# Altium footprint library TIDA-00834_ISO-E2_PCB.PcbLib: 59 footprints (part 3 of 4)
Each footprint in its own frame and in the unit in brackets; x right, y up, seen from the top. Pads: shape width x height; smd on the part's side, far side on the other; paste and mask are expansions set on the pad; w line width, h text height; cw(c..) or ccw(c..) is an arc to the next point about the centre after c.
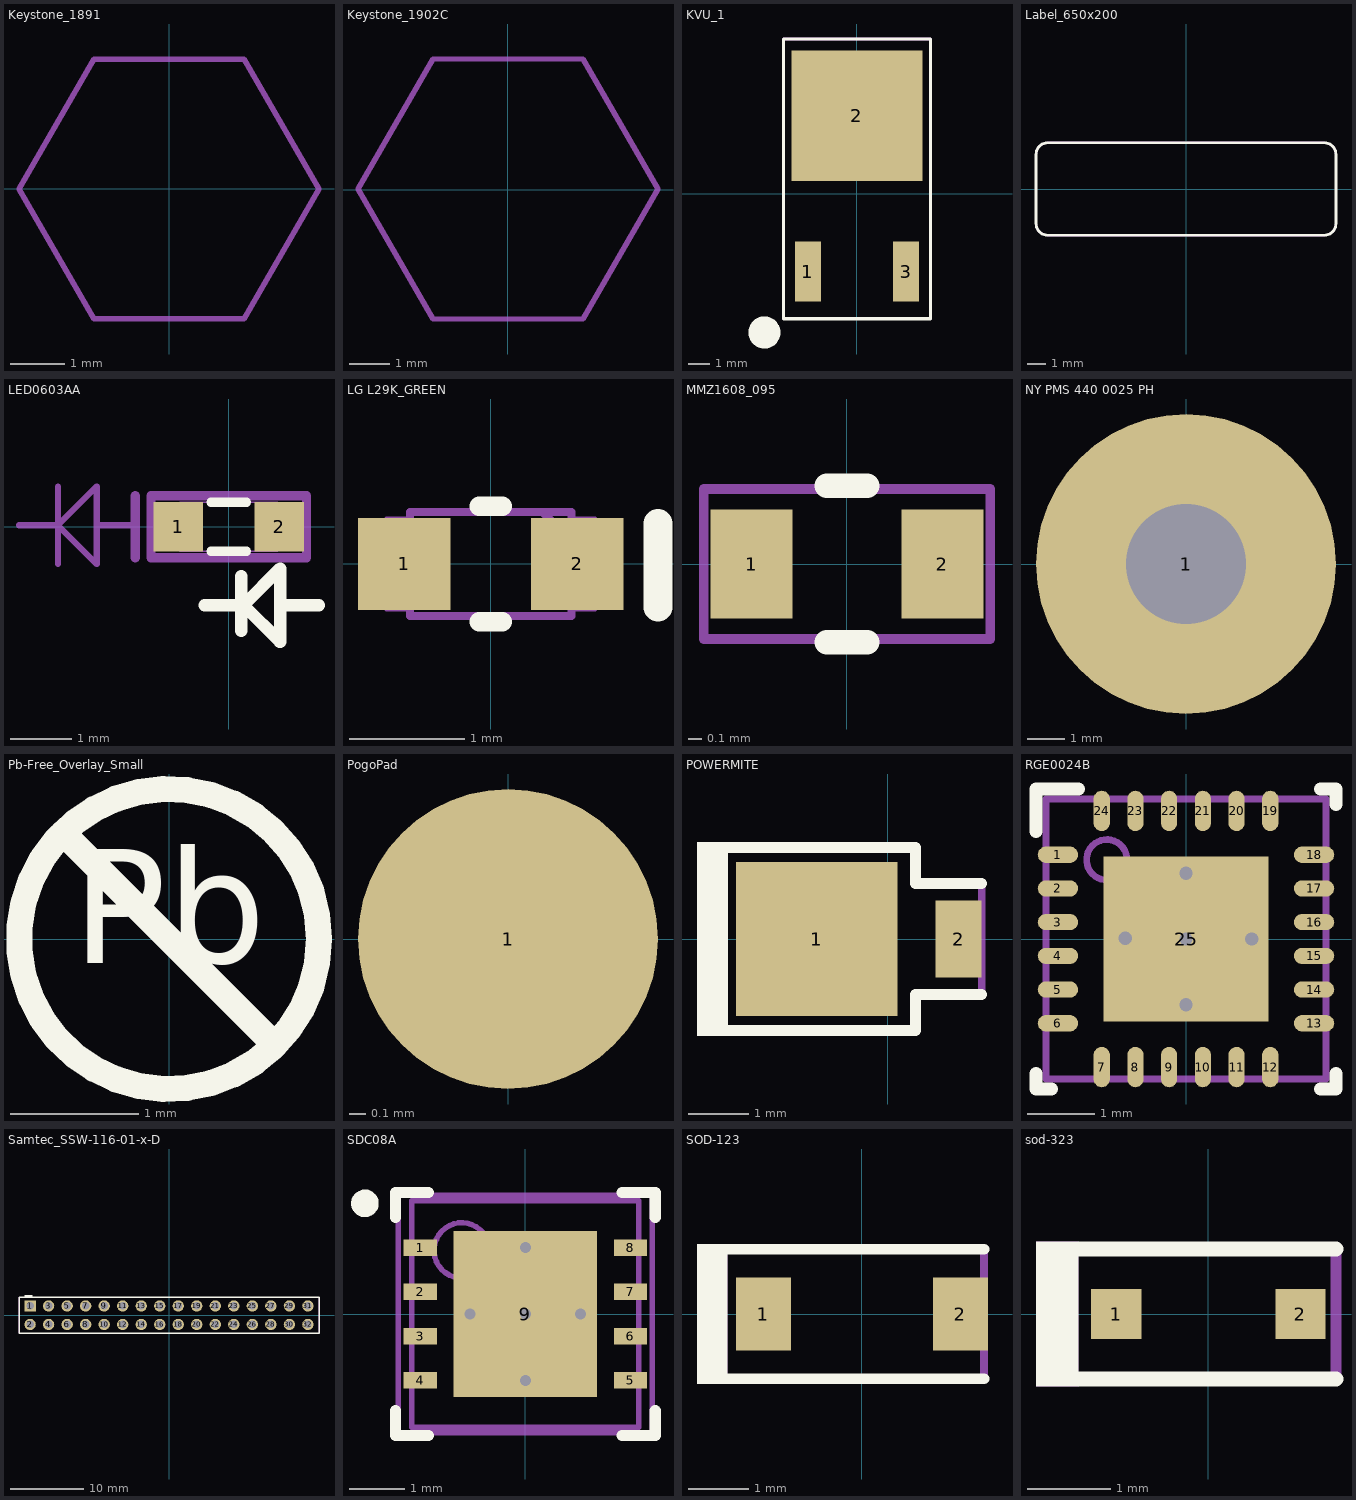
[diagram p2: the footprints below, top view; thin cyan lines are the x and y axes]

## Keystone_1891 [mm] "3/16 Hex Female Standoff"
height 6.35
Mechanical 5:
  lines w0.1: -2.742,0 -1.371,-2.375 0,-2.375 1.371,-2.375 2.742,0 1.371,2.375 0,2.375 -1.371,2.375 -2.742,0
  text ".Designator" at -0.66,-0.174 h0.64
3D body "keystone-PN1891.stp": height 6.22, standoff -0.13, extent -2.742,-2.375 2.742,2.375

## Keystone_1902C [mm] "Hex Standoff, 4-40 threaded, nylon"
height 12.7
Mechanical 5:
  lines w0.127: -3.69,0.012 -1.843,-3.188 1.852,-3.188 3.7,0.012 1.852,3.212 -1.843,3.212 -3.69,0.012
  text ".Designator" at -1.524,-0.508 h1.02
3D body "Keystone_1902C.stp": height 12.73, standoff 0.03, extent -3.682,-3.2 3.708,3.2

## KVU_1 [mm]
height 2.39
pads (3):
  rect 1.2x2.8 smd: 1(-2.29,-3.635) 3(2.29,-3.635)
  rect 6.096x6.096 smd: 2(0,3.635)
Top Overlay:
  circle w0.889: c-4.318,-6.477 r0.305
  lines w0.152: -3.429,-5.841 -3.429,7.216 3.429,7.216 3.429,-5.841 -3.429,-5.841
Mechanical 5:
  lines w0.127: -3.429,-5.841 3.429,-5.841 3.429,7.216 -3.429,7.216 -3.429,-5.841
  text ".Designator" at 0,1.524 h0.64

## Label_650x200 [mm] "Thermal Transfer Label"
height 0.025
Top Overlay:
  lines w0.152: -8.255,-1.905 ccw(c-7.62,-1.905) -7.62,-2.54 7.62,-2.54 ccw(c7.62,-1.905) 8.255,-1.905 8.255,1.905 ccw(c7.62,1.905) 7.62,2.54 -7.62,2.54 ccw(c-7.62,1.905) -8.255,1.905 -8.255,-1.905
Mechanical 5:
  lines w0.127: -8.255,-1.905 ccw(c-7.62,-1.905) -7.62,-2.54 7.62,-2.54 ccw(c7.62,-1.905) 8.255,-1.905 8.255,1.905 ccw(c7.62,1.905) 7.62,2.54 -7.62,2.54 ccw(c-7.62,1.905) -8.255,1.905 -8.255,-1.905
  text ".Designator" at -1.524,-0.508 h0.64
3D body: height 0.03, standoff 0, extent -8.256,-2.541 8.256,2.541

## LED0603AA [mil]
height 118.11
pads (2):
  rect 32x32 smd: 1(-32.48,0) 2(32.48,0)
Top Overlay:
  lines w6: -11.42,-15.75 11.42,-15.75 ; -11.42,15.75 11.42,15.75
  lines w8: -15.58,-50.44 9.42,-50.44 33,-26.85 33,-73.81 ; 8,-66.85 8,-31.85 ; 9.62,-50.44 33,-73.81 ; 32.79,-73.81 33,-73.81 ; 33,-50.33 58,-50.33
Mechanical 5:
  lines w6: -60,-20 -60,20 ; -50,-20 50,-20 50,20 -50,20 -50,-20
  text ".designator" at -36,-57 h25
Mechanical 15:
  lines w1: -31.5,-15.75 31.5,-15.75 31.5,15.75 -31.5,15.75 -31.5,-15.75
  lines w3.94: -134.79,0.96 -109.79,0.96 ; -109.79,-24.04 -109.79,25.96 ; -84.79,0.96 -59.79,0.96 ; -109.79,0.96 -84.79,25.96 -84.79,-24.04 -109.79,0.96

## LG L29K_GREEN [mm] "OSRAM"
height 0.67
pads (2):
  rect 0.8x0.8 smd: 1(-0.75,0) 2(0.75,0)
Top Overlay:
  lines w0.17: -0.1,-0.5 0.1,-0.5 ; -0.1,0.5 0.1,0.5
  lines w0.25: 1.45,-0.375 1.45,0.35
Top Paste:
  rectangle: 0.5,-0.35 1.1,0.35
  rectangle: -1.1,-0.35 -0.5,0.35
Mechanical 5:
  lines w0.07: 0.7,0.375 0.9,0.375 0.9,-0.375 0.7,-0.375 ; 0.7,-0.375 0.7,-0.45 -0.7,-0.45 -0.7,-0.375 -0.9,-0.375 -0.9,0.375 -0.7,0.375 -0.7,0.45 0.7,0.45 ; 0.7,-0.375 0.7,0.2 ; 0.7,0.2 0.7,0.45 ; 0.7,0.2 0.45,0.45 0.7,0.45
  text ".Designator" at -0.889,0.762 h0.64
3D body: height 0.67, standoff 0.65, extent 0.451,0.201 0.699,0.449
3D body: height 0.67, standoff 0.18, extent -0.699,-0.449 0.699,0.449
3D body: height 0.18, standoff 0, extent -0.699,-0.449 0.699,0.449
3D body: height 0.18, standoff 0, extent 0.701,-0.374 0.899,0.374
3D body: height 0.18, standoff 0, extent -0.899,-0.374 -0.701,0.374

## MMZ1608_095 [mm] "TDK"
height 0.95
pads (2):
  rect 0.6x0.8 smd: 1(-0.7,0) 2(0.7,0)
Top Overlay:
  lines w0.18: -0.15,-0.575 0.15,-0.575 ; -0.15,0.575 0.15,0.575
Mechanical 5:
  lines w0.07: -1.05,-0.55 -1.05,0.55 1.05,0.55 1.05,-0.55 -1.05,-0.55
  text ".Designator" at 0.787,0.317 h0.64
3D body: height 0.95, standoff 0, extent -0.874,-0.474 -0.501,0.474
3D body: height 0.95, standoff 0, extent -0.499,-0.474 0.499,0.474
3D body: height 0.95, standoff 0, extent 0.501,-0.474 0.874,0.474

## NY PMS 440 0025 PH [mm] "4-40 nylon screw and mounting hole"
height 1.905
pads (1):
  round 8 hole 3.2: 1(0,0)
Mechanical 5:
  circle w0.127: c0,0 r3.789
  text ".Designator" at -0.61,-0.453 h0.64
3D body "B_F_NY PMS 440 0025 PH.stp": height 2.69, standoff -8.74, extent -3.302,-3.3 3.296,3.3

## Pb-Free_Overlay_Small [mm]
Top Overlay:
  circle w0.203: c0,0 r1.168
  lines w0.203: -0.826,0.826 0.826,-0.826
  text "Pb" at -0.752,-0.48 h1.52

## PogoPad [mil] "No Solder Paste"
pads (1):
  round 70 smd paste-35: 1(0,0)

## POWERMITE [mil] "On Semi recommended land pattern, 457-04.pdf Rev 04E dated 2008-11-26"
height 45.28
pads (2):
  rect 105x100 smd: 1(-46,0)
  rect 30x50 smd: 2(46,0)
Top Overlay:
  rectangle: -123.96,-63 -103.96,63
  lines w7: -109.7,-59.5 -19,-59.5 18,-59.5 18,-36 61,-36 ; -109.7,59.5 -19,59.5 18,59.5 18,36 61,36
Mechanical 5:
  rectangle: -123.96,-63 -103.96,63
  lines w5: -109.7,-59.5 -19,-59.5 18,-59.5 18,-36 61,-36 61,36 18,36 18,59.5 -19,59.5 -109.7,59.5
  text ".Designator" at -51,25 h25
3D body "PowerMite.stp": height 45.31, standoff 0, extent -94.48,-40.35 59.06,40.36

## RGE0024B [mm] "QFN, 24-Leads, Body 4x4mm, Pitch 0.5mm, Thermal Pad 2.45x2.45mm, TI Recommended"
height 1
pads (25):
  oval 0.6x0.24 smd: 1(-1.9,1.25) 2(-1.9,0.75) 3(-1.9,0.25) 4(-1.9,-0.25) 5(-1.9,-0.75) 6(-1.9,-1.25) 13(1.9,-1.25) 14(1.9,-0.75) 15(1.9,-0.25) 16(1.9,0.25) 17(1.9,0.75) 18(1.9,1.25)
  oval 0.24x0.6 smd: 7(-1.25,-1.9) 8(-0.75,-1.9) 9(-0.25,-1.9) 10(0.25,-1.9) 11(0.75,-1.9) 12(1.25,-1.9) 19(1.25,1.9) 20(0.75,1.9) 21(0.25,1.9) 22(-0.25,1.9) 23(-0.75,1.9) 24(-1.25,1.9)
  rect 2.45x2.45 smd paste-1.225: 25(0,0)
via 0,-0.975 diameter 0.5 hole 0.2
via 0.975,0 diameter 0.5 hole 0.2
via 0,0 diameter 0.5 hole 0.2
via -0.899,0.008 diameter 0.5 hole 0.2
via 0,0.975 diameter 0.5 hole 0.2
Top Overlay:
  lines w0.2: -2.225,-2 -2.225,-2.225 -2,-2.225 ; -2.225,1.6 -2.225,2.225 -1.6,2.225 ; 2,-2.225 2.225,-2.225 2.225,-2 ; 2,2.225 2.225,2.225 2.225,2
Top Paste:
  rectangle: 0.1,-1.184 1.184,-0.1
  region: -0.1,-0.1 -1.184,-0.1 -1.184,-1.184 -0.1,-1.184
  region: -0.1,1.184 -1.184,1.184 -1.184,0.1 -0.1,0.1
  rectangle: 0.1,0.1 1.184,1.184
Mechanical 5:
  circle w0.1: c-1.175,1.175 r0.3
  lines w0.1: -2.075,-2.075 2.075,-2.075 2.075,2.075 -2.075,2.075 -2.075,-2.075
  text ".Designator" at 0.672,0.274 h0.64
3D body: height 1, standoff 0, extent -2.075,-2.075 2.075,2.075
3D body: height 1.01, standoff 0.5, extent -1.474,0.876 -0.876,1.474

## Samtec_SSW-116-01-x-D [mm] "Receptacle, 2.54mm, 16x2, TH"
height 8.64
pads (32):
  rect 1.55x1.55 hole 1.04: 1(-19.05,1.27)
  round 1.55 hole 1.04: 2(-19.05,-1.27) 3(-16.51,1.27) 4(-16.51,-1.27) 5(-13.97,1.27) 6(-13.97,-1.27) 7(-11.43,1.27) 8(-11.43,-1.27) 9(-8.89,1.27) 10(-8.89,-1.27) 11(-6.35,1.27) 12(-6.35,-1.27) 13(-3.81,1.27) 14(-3.81,-1.27) 15(-1.27,1.27) 16(-1.27,-1.27) 17(1.27,1.27) 18(1.27,-1.27) 19(3.81,1.27) 20(3.81,-1.27) 21(6.35,1.27) 22(6.35,-1.27) 23(8.89,1.27) 24(8.89,-1.27) 25(11.43,1.27) 26(11.43,-1.27) 27(13.97,1.27) 28(13.97,-1.27) 29(16.51,1.27) 30(16.51,-1.27) 31(19.05,1.27) 32(19.05,-1.27)
Top Overlay:
  rectangle: -19.8,2.476 -18.7,2.8
  lines w0.2: -20.574,-2.476 20.574,-2.476 20.574,2.476 -20.574,2.476 -20.574,-2.476
Mechanical 5:
  lines w0.1: -20.574,-2.476 -20.574,2.476 20.574,2.476 20.574,-2.476 -20.574,-2.476
  text ".Designator" at 1.118,0.58 h1.85
3D body "SSW-116-01-G-D.stp": height 8.51, standoff -2.64, extent -20.574,-2.476 20.574,2.477

## SDC08A [mm] "SON, 8-Leads, Body 4x4mm, Pitch 0.8mm, NSC Recommended"
height 0.8
pads (9):
  rect 0.6x0.3 smd paste-0.15 mask+0.051: 1(-1.9,1.2) 2(-1.9,0.4) 3(-1.9,-0.4) 4(-1.9,-1.2) 5(1.9,-1.2) 6(1.9,-0.4) 7(1.9,0.4) 8(1.9,1.2)
  rect 2.6x3 smd paste-1.5 mask+0.051: 9(0,0)
via 0,-1.2 diameter 0.5 hole 0.2
via 0,1.2 diameter 0.5 hole 0.2
via 1,0 diameter 0.5 hole 0.2
via 0,0 diameter 0.5 hole 0.2
via -1,0 diameter 0.5 hole 0.2
Top Overlay:
  circle w0.25: c-2.9,2 r0.125
  lines w0.2: -2.35,-1.75 -2.35,-2.2 -1.75,-2.2 ; -2.35,1.75 -2.35,2.2 -1.75,2.2 ; 1.75,-2.2 2.35,-2.2 2.35,-1.75 ; 1.75,2.2 2.35,2.2 2.35,1.75
Top Paste:
  region: -1.7,1.35 -2.4,1.35 -2.4,1.05 -1.7,1.05
  region: -1.7,0.55 -2.4,0.55 -2.4,0.25 -1.7,0.25
  region: -1.7,-0.25 -2.4,-0.25 -2.4,-0.55 -1.7,-0.55
  region: -1.7,-1.05 -2.4,-1.05 -2.4,-1.35 -1.7,-1.35
  rectangle: 1.7,-1.35 2.4,-1.05
  rectangle: 1.7,-0.55 2.4,-0.25
  rectangle: 1.7,0.25 2.4,0.55
  rectangle: 1.7,1.05 2.4,1.35
  rectangle: -1.2,0.1 -0.1,1.4
  region: 1.2,1.4 0.1,1.4 0.1,0.1 1.2,0.1
  region: 1.2,-0.1 0.1,-0.1 0.1,-1.4 1.2,-1.4
  rectangle: -1.2,-1.4 -0.1,-0.1
Mechanical 5:
  text ".Designator" at -0.644,-0.305 h0.64
Mechanical 13:
  circle w0.1: c-1.15,1.15 r0.5
  lines w0.1: -2.05,-2.05 -2.05,2.05 2.05,2.05 2.05,-2.05 -2.05,-2.05
Mechanical 15:
  lines w0.1: -0.5,0 0.5,0 ; 0,-0.5 0,0.5 ; -2.3,-2.15 -2.3,2.15 2.3,2.15 2.3,-2.15 -2.3,-2.15
3D body: height 0.8, standoff 0, extent -2.05,-2.05 2.05,2.05

## SOD-123 [mm] "On Semi recommended land pattern"
height 1.35
pads (2):
  rect 0.915x1.22 smd: 1(-1.637,0) 2(1.637,0)
Top Overlay:
  rectangle: -2.743,-1.168 -2.235,1.168
  lines w0.178: -2.413,-1.079 2.032,-1.079 ; -2.413,1.079 2.032,1.079
Mechanical 5:
  rectangle: -2.743,-1.168 -2.235,1.168
  lines w0.127: -2.413,-1.079 2.032,-1.079 2.032,1.079 -2.413,1.079
  text ".Designator" at 0.787,0.33 h0.64
3D body "SOD-123.stp": height 1.35, standoff 0, extent -1.932,-0.9 1.932,0.9

## sod-323 [mm] "NXP recommended land pattern"
height 1.15
pads (2):
  rect 0.6x0.6 smd: 1(-1.1,0) 2(1.1,0)
Top Overlay:
  rectangle: -2.057,-0.864 -1.549,0.864
  lines w0.178: -1.803,-0.775 0.1,-0.775 1.525,-0.775 ; -1.803,0.775 0.1,0.775 1.525,0.775
Mechanical 5:
  rectangle: -2.057,-0.864 -1.549,0.864
  lines w0.127: -1.803,-0.775 0.1,-0.775 1.525,-0.775 1.525,0.775 0.1,0.775 -1.803,0.775
  text ".Designator" at -0.965,-0.356 h0.64
3D body "SOD-323.stp": height 1.1, standoff 0, extent -1.3,-0.675 1.3,0.675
